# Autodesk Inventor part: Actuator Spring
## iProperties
Created: 2009-03
Part Number: Actuator Spring
Document SubType Name: Modeling
Designer: tangg
Density: 7.84 g/cm^3
Material: Steel, High Strength Low Alloy
Mass: 4.28111 g
Surface Area: 12.5295 cm^2
Volume: 0.54606 cm^3
Author: tangg
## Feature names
1. Sweep1
